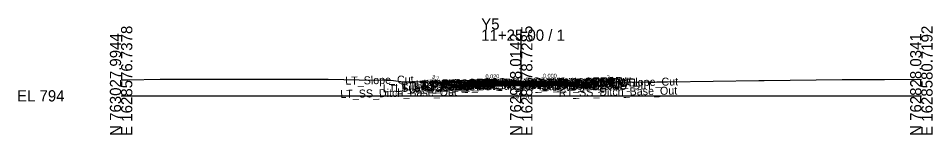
# Model space of a CAD drawing. Extents: x -26 to 203, y -10 to 6017.
# Drawn here: x -25.7 to 202.8, y 2490.3 to 2519.3 of the extents above; entities that cross this region are included whole.
import ezdxf

# ---------------------------------------------------------------- set-up
doc = ezdxf.new("R2010")
doc.units = 0
for name, color, linetype in [('Default', 7, 'Continuous'), ('Exist Cross Section Cell', 7, 'Continuous'), ('Exist XS Center Line Elevation Label', 7, 'Continuous'), ('Exist XS Ground Line', 7, 'Continuous'), ('Prop CMT Concrete Structures', 7, 'Continuous'), ('Prop CMT Pvmt Course 1', 7, 'Continuous'), ('Prop CMT Pvmt Course 2', 7, 'Continuous'), ('Prop CMT Pvmt Course 2 Wedge', 7, 'Continuous'), ('Prop CMT Pvmt Course 3', 7, 'Continuous'), ('Prop CMT Pvmt Course 3 Wedge', 7, 'Continuous'), ('Prop CMT Pvmt Surface', 7, 'Continuous'), ('Prop CMT Pvmt Surface Shoulder', 7, 'Continuous'), ('Prop CMT Pvmt Wedge Surface 1', 7, 'Continuous'), ('Prop CMT Pvmt Wedge Surface 2', 7, 'Continuous'), ('Prop CMT Pvmt Wedge Surface 3', 7, 'Continuous'), ('Prop CMT Shld Paved Course 1', 7, 'Continuous'), ('Prop CMT Shld Paved Course 2', 7, 'Continuous'), ('Prop CMT Shld Paved Course 3', 7, 'Continuous'), ('Prop CMT Slope Grass', 7, 'Continuous'), ('Prop CMT Subgrade Earthwork', 7, 'Continuous'), ('Prop XS SE Text', 7, 'Continuous'), ('Prop XS Side Slope Text', 7, 'Continuous'), ('Scratch_Level_0', 7, 'Continuous')]:
    doc.layers.add(name, color=color, linetype=linetype)

msp = doc.modelspace()

# ---------------------------------------------------------------- linework, layer by layer
at = {"layer": 'Exist Cross Section Cell'}
for p, q in [((100, 2500), (100, 2516.53)), ((0, 2500), (100, 2500)), ((100, 2500), (200, 2500))]:
    msp.add_line(p, q, dxfattribs=at)
at = {"layer": 'Exist XS Ground Line'}
msp.add_lwpolyline([(0, 2504.01), (1.66, 2504.01), (9.73, 2504.19), (27.39, 2504.19), (31.31, 2504.17), (49.8, 2504.18), (51.24, 2504.19), (51.73, 2504.17), (63.45, 2503.88), (65.21, 2504.02), (66.87, 2503.95), (69.94, 2503.53), (70.91, 2503.52), (71.43, 2503.52), (81.1, 2503.58), (83.96, 2503.68), (84.97, 2503.63), (85.34, 2503.5), (90.8, 2503.71), (92.73, 2503.74), (100, 2503.7), (102.03, 2503.68), (114.82, 2503.37), (115.18, 2503.38), (115.53, 2503.38), (116.02, 2503.38), (116.77, 2503.4), (133.86, 2503.46), (135.27, 2503.47), (136.52, 2503.47), (159.42, 2503.78), (159.75, 2503.79), (160.18, 2503.79), (160.75, 2503.8), (180.25, 2504.05), (190.83, 2504.05), (200, 2504.12)], dxfattribs=at)
at = {"layer": 'Prop CMT Concrete Structures'}
for points in [[(83.69, 2503.21), (83.69, 2502.63), (85.69, 2502.63)], [(85.69, 2503.21), (84.69, 2503.13), (83.69, 2503.21)], [(85.69, 2502.63), (85.69, 2503.21)], [(114.36, 2502.92), (114.36, 2503.5)], [(116.36, 2503.5), (116.36, 2502.92), (114.36, 2502.92)], [(114.36, 2503.5), (115.36, 2503.42), (116.36, 2503.5)]]:
    msp.add_lwpolyline(points, dxfattribs=at)
at = {"layer": 'Prop CMT Pvmt Course 1'}
for points in [[(100, 2503.5), (85.69, 2503.21)], [(100, 2503.5), (85.69, 2503.21)], [(85.69, 2502.96), (100, 2503.25)], [(85.69, 2503.21), (85.69, 2503.09)], [(85.69, 2503.21), (85.69, 2502.96)], [(100, 2503.37), (100, 2503.5)], [(100, 2503.25), (100, 2503.5)], [(100, 2503.5), (114.35, 2503.5)], [(100, 2503.37), (100, 2503.5)], [(100, 2503.5), (114.36, 2503.5)], [(100, 2503.25), (100, 2503.5)], [(114.36, 2503.25), (100, 2503.25)], [(114.36, 2503.5), (114.36, 2503.25)]]:
    msp.add_lwpolyline(points, dxfattribs=at)
at = {"layer": 'Prop CMT Pvmt Course 2'}
for points in [[(100, 2503.25), (85.69, 2502.96)], [(85.69, 2502.96), (85.69, 2502.63)], [(85.69, 2502.63), (100, 2502.92)], [(100, 2502.92), (100, 2503.25)], [(100, 2502.92), (100, 2503.25)], [(100, 2503.25), (114.36, 2503.25)], [(114.36, 2502.92), (100, 2502.92)], [(114.36, 2503.25), (114.36, 2502.92)]]:
    msp.add_lwpolyline(points, dxfattribs=at)
at = {"layer": 'Prop CMT Pvmt Course 2 Wedge'}
for points in [[(100, 2503.25), (85.69, 2502.96)], [(100, 2503.25), (114.35, 2503.25)]]:
    msp.add_lwpolyline(points, dxfattribs=at)
at = {"layer": 'Prop CMT Pvmt Course 3'}
msp.add_line((116.36, 2502.92), (116.86, 2502.92), dxfattribs=at)
for points in [[(100, 2502.92), (85.69, 2502.63)], [(85.69, 2502.63), (85.69, 2502.3)], [(85.69, 2502.3), (100, 2502.58)], [(100, 2502.58), (100, 2502.92)], [(100, 2502.92), (114.36, 2502.92)], [(100, 2502.58), (100, 2502.92)], [(114.36, 2502.58), (100, 2502.58)], [(114.36, 2502.92), (114.36, 2502.58)]]:
    msp.add_lwpolyline(points, dxfattribs=at)
at = {"layer": 'Prop CMT Pvmt Course 3 Wedge'}
for points in [[(100, 2502.92), (85.69, 2502.63)], [(100, 2502.92), (114.35, 2502.92)]]:
    msp.add_lwpolyline(points, dxfattribs=at)
at = {"layer": 'Prop CMT Pvmt Surface'}
for points in [[(100, 2503.5), (85.69, 2503.21)], [(100, 2503.5), (85.69, 2503.21)], [(100, 2503.5), (114.36, 2503.5)], [(100, 2503.5), (114.35, 2503.5)]]:
    msp.add_lwpolyline(points, dxfattribs=at)
at = {"layer": 'Prop CMT Pvmt Surface Shoulder'}
for points in [[(85.69, 2503.21), (85.69, 2503.21)], [(114.36, 2503.5), (114.36, 2503.5)]]:
    msp.add_lwpolyline(points, dxfattribs=at)
at = {"layer": 'Prop CMT Pvmt Wedge Surface 1'}
msp.add_lwpolyline([(85.69, 2503.09), (85.69, 2503.21)], dxfattribs=at)
at = {"layer": 'Prop CMT Pvmt Wedge Surface 2'}
for points in [[(100, 2503.25), (85.69, 2502.96)], [(85.69, 2502.96), (85.69, 2503.21)], [(100, 2503.25), (100, 2503.5)], [(100, 2503.25), (100, 2503.5)], [(100, 2503.25), (100, 2503.5)], [(100, 2503.25), (100, 2503.5)], [(100, 2503.25), (114.35, 2503.25)]]:
    msp.add_lwpolyline(points, dxfattribs=at)
at = {"layer": 'Prop CMT Pvmt Wedge Surface 3'}
for points in [[(85.69, 2502.63), (85.69, 2503.21)], [(100, 2502.92), (85.69, 2502.63)], [(100, 2502.92), (100, 2503.5)], [(100, 2502.92), (100, 2503.5)], [(100, 2502.92), (100, 2503.5)], [(100, 2502.92), (100, 2503.5)], [(100, 2502.92), (114.35, 2502.92)]]:
    msp.add_lwpolyline(points, dxfattribs=at)
at = {"layer": 'Prop CMT Shld Paved Course 1'}
for points in [[(85.69, 2503.21), (85.69, 2503.21)], [(85.69, 2502.96), (85.69, 2503.21)], [(114.36, 2503.5), (114.36, 2503.5)], [(114.36, 2503.25), (114.36, 2503.5)]]:
    msp.add_lwpolyline(points, dxfattribs=at)
at = {"layer": 'Prop CMT Shld Paved Course 2'}
for p, q in [((83.69, 2502.63), (85.69, 2502.63)), ((116.36, 2502.92), (114.36, 2502.92))]:
    msp.add_line(p, q, dxfattribs=at)
for points in [[(85.69, 2502.63), (85.69, 2502.96)], [(114.36, 2502.92), (114.36, 2503.25)]]:
    msp.add_lwpolyline(points, dxfattribs=at)
at = {"layer": 'Prop CMT Shld Paved Course 3'}
for p, q in [((117.2, 2502.58), (114.36, 2502.58)), ((82.85, 2502.29), (85.69, 2502.3))]:
    msp.add_line(p, q, dxfattribs=at)
for points in [[(85.69, 2502.63), (83.69, 2502.63), (83.19, 2502.63), (82.85, 2502.29)], [(85.69, 2502.3), (85.69, 2502.63)], [(114.36, 2502.58), (114.36, 2502.92)], [(114.36, 2502.92), (116.86, 2502.92), (116.86, 2502.92), (117.2, 2502.58)]]:
    msp.add_lwpolyline(points, dxfattribs=at)
at = {"layer": 'Prop CMT Slope Grass'}
for points in [[(83.69, 2503.21), (78.69, 2503.31), (77.95, 2503.56)], [(116.36, 2503.5), (121.36, 2503.6), (121.91, 2503.42)]]:
    msp.add_lwpolyline(points, dxfattribs=at)
at = {"layer": 'Prop CMT Subgrade Earthwork'}
for p, q in [((82.85, 2502.29), (81.9, 2503.25)), ((114.36, 2502.58), (117.2, 2502.58)), ((117.2, 2502.58), (118.16, 2503.53)), ((85.69, 2502.3), (82.85, 2502.29))]:
    msp.add_line(p, q, dxfattribs=at)
for points in [[(100, 2502.58), (85.69, 2502.3)], [(100, 2502.58), (114.36, 2502.58)]]:
    msp.add_lwpolyline(points, dxfattribs=at)

# ---------------------------------------------------------------- texts
at = {"layer": 'Default'}
msp.add_text('-', height=0.0001, dxfattribs=at).set_placement((0, 2500))
at = {"layer": 'Exist Cross Section Cell'}
for s, p in [('Y5', (90, 2516.53)), ('11+25.00 / 1', (90, 2513.73)), ('EL 794', (-26, 2498.6))]:
    msp.add_text(s, height=2.8, dxfattribs=at).set_placement(p)
for s, p in [('E 1628576.7378', (2.8, 2490)), ('E 1628578.7285', (102.8, 2490)), ('E 1628580.7192', (202.8, 2490)), ('N 763027.9944', (0, 2490)), ('N 762928.0142', (100, 2490)), ('N 762828.0341', (200, 2490))]:
    msp.add_text(s, height=2.8, rotation=90, dxfattribs=at).set_placement(p)
at = {"layer": 'Exist XS Center Line Elevation Label'}
msp.add_text('797.70', height=1.2, dxfattribs=at).set_placement((97.57, 2499.1))
at = {"layer": 'Prop XS SE Text'}
msp.add_text('0.020', height=1, rotation=1.1458, dxfattribs=at).set_placement((91.08, 2504.32))
msp.add_text('0.000', height=1, dxfattribs=at).set_placement((105.43, 2504.5))
at = {"layer": 'Prop XS Side Slope Text'}
for p in [(77.57, 2504.37), (121.15, 2504.28)]:
    msp.add_text('3:1', height=1, rotation=341.5651, dxfattribs=at).set_placement(p)
at = {"layer": 'Scratch_Level_0'}
for s, p in [('LT_Slope_Cut', (56.04, 2502.76)), ('LT_Sub_OSS_DLT', (65.44, 2500.89)), ('LT_Sub_Trench_Out', (68.49, 2500.95)), ('LT_GS_OS_CTL', (70.09, 2501.6)), ('LT_PS3_Shelf_Out', (70.61, 2501.33)), ('LT_PV2_OEEOP_W', (73.13, 2501.71)), ('LT_PV3_OEEOP_W', (73.13, 2501.38)), ('LT_PV1_OEEOP_W', (73.7, 2501.85)), ('LT_PS3_OEOP', (75.36, 2501.42)), ('LT_PV1_OEEOP', (75.59, 2502.01)), ('LT_PS2_OEOP', (75.7, 2501.76)), ('LT_Sub_OEOT', (75.8, 2501.1)), ('LT_PV2_OEOT', (75.89, 2501.77)), ('LT_PV3_OEOT', (75.89, 2501.43)), ('LT_PV1_OEOT', (76.46, 2502.03)), ('LT_PS1_OEOP', (76.52, 2502.03)), ('RT_PV1_PGL_W', (89.86, 2502.17)), ('LT_PV1_PGL_W', (89.91, 2502.17)), ('Sub_PGL', (93.83, 2501.46)), ('PV2_PGL', (93.93, 2502.13)), ('PV3_PGL', (93.93, 2501.79)), ('PV1_PGL', (94.49, 2502.39)), ('RT_Sub_Trench_Out', (99.98, 2501.24)), ('RT_PS3_Shelf_Out', (101.42, 2501.61)), ('RT_PV2_OEEOP_W', (101.75, 2502)), ('RT_PV3_OEEOP_W', (101.75, 2501.66)), ('RT_PV1_OEEOP_W', (102.31, 2502.13)), ('RT_PV1_OEEOP', (104.2, 2502.3)), ('RT_Sub_OEOT', (104.42, 2501.38)), ('RT_PV2_OEOT', (104.51, 2502.05)), ('RT_PV3_OEOT', (104.51, 2501.72)), ('RT_PS2_OEOP', (104.83, 2502.05)), ('RT_PV1_OEOT', (105.08, 2502.31)), ('RT_PS1_OEOP', (105.14, 2502.31)), ('RT_PS3_OEOP', (105.17, 2501.71)), ('RT_GS_OS_CTL', (108.71, 2501.89)), ('RT_Sub_OSS_DLT', (109.42, 2501.18)), ('RT_Slope_Cut', (121.69, 2502.25)), ('LT_SS_Ditch_Base_Out', (54.8, 2499.45)), ('RT_SS_Ditch_Base_Out', (109.42, 2499.74))]:
    msp.add_text(s, height=2, rotation=1.1458, dxfattribs=at).set_placement(p)

doc.saveas('drawing.dxf')
